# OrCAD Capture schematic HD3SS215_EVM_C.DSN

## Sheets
1 Page 1 Cover Page
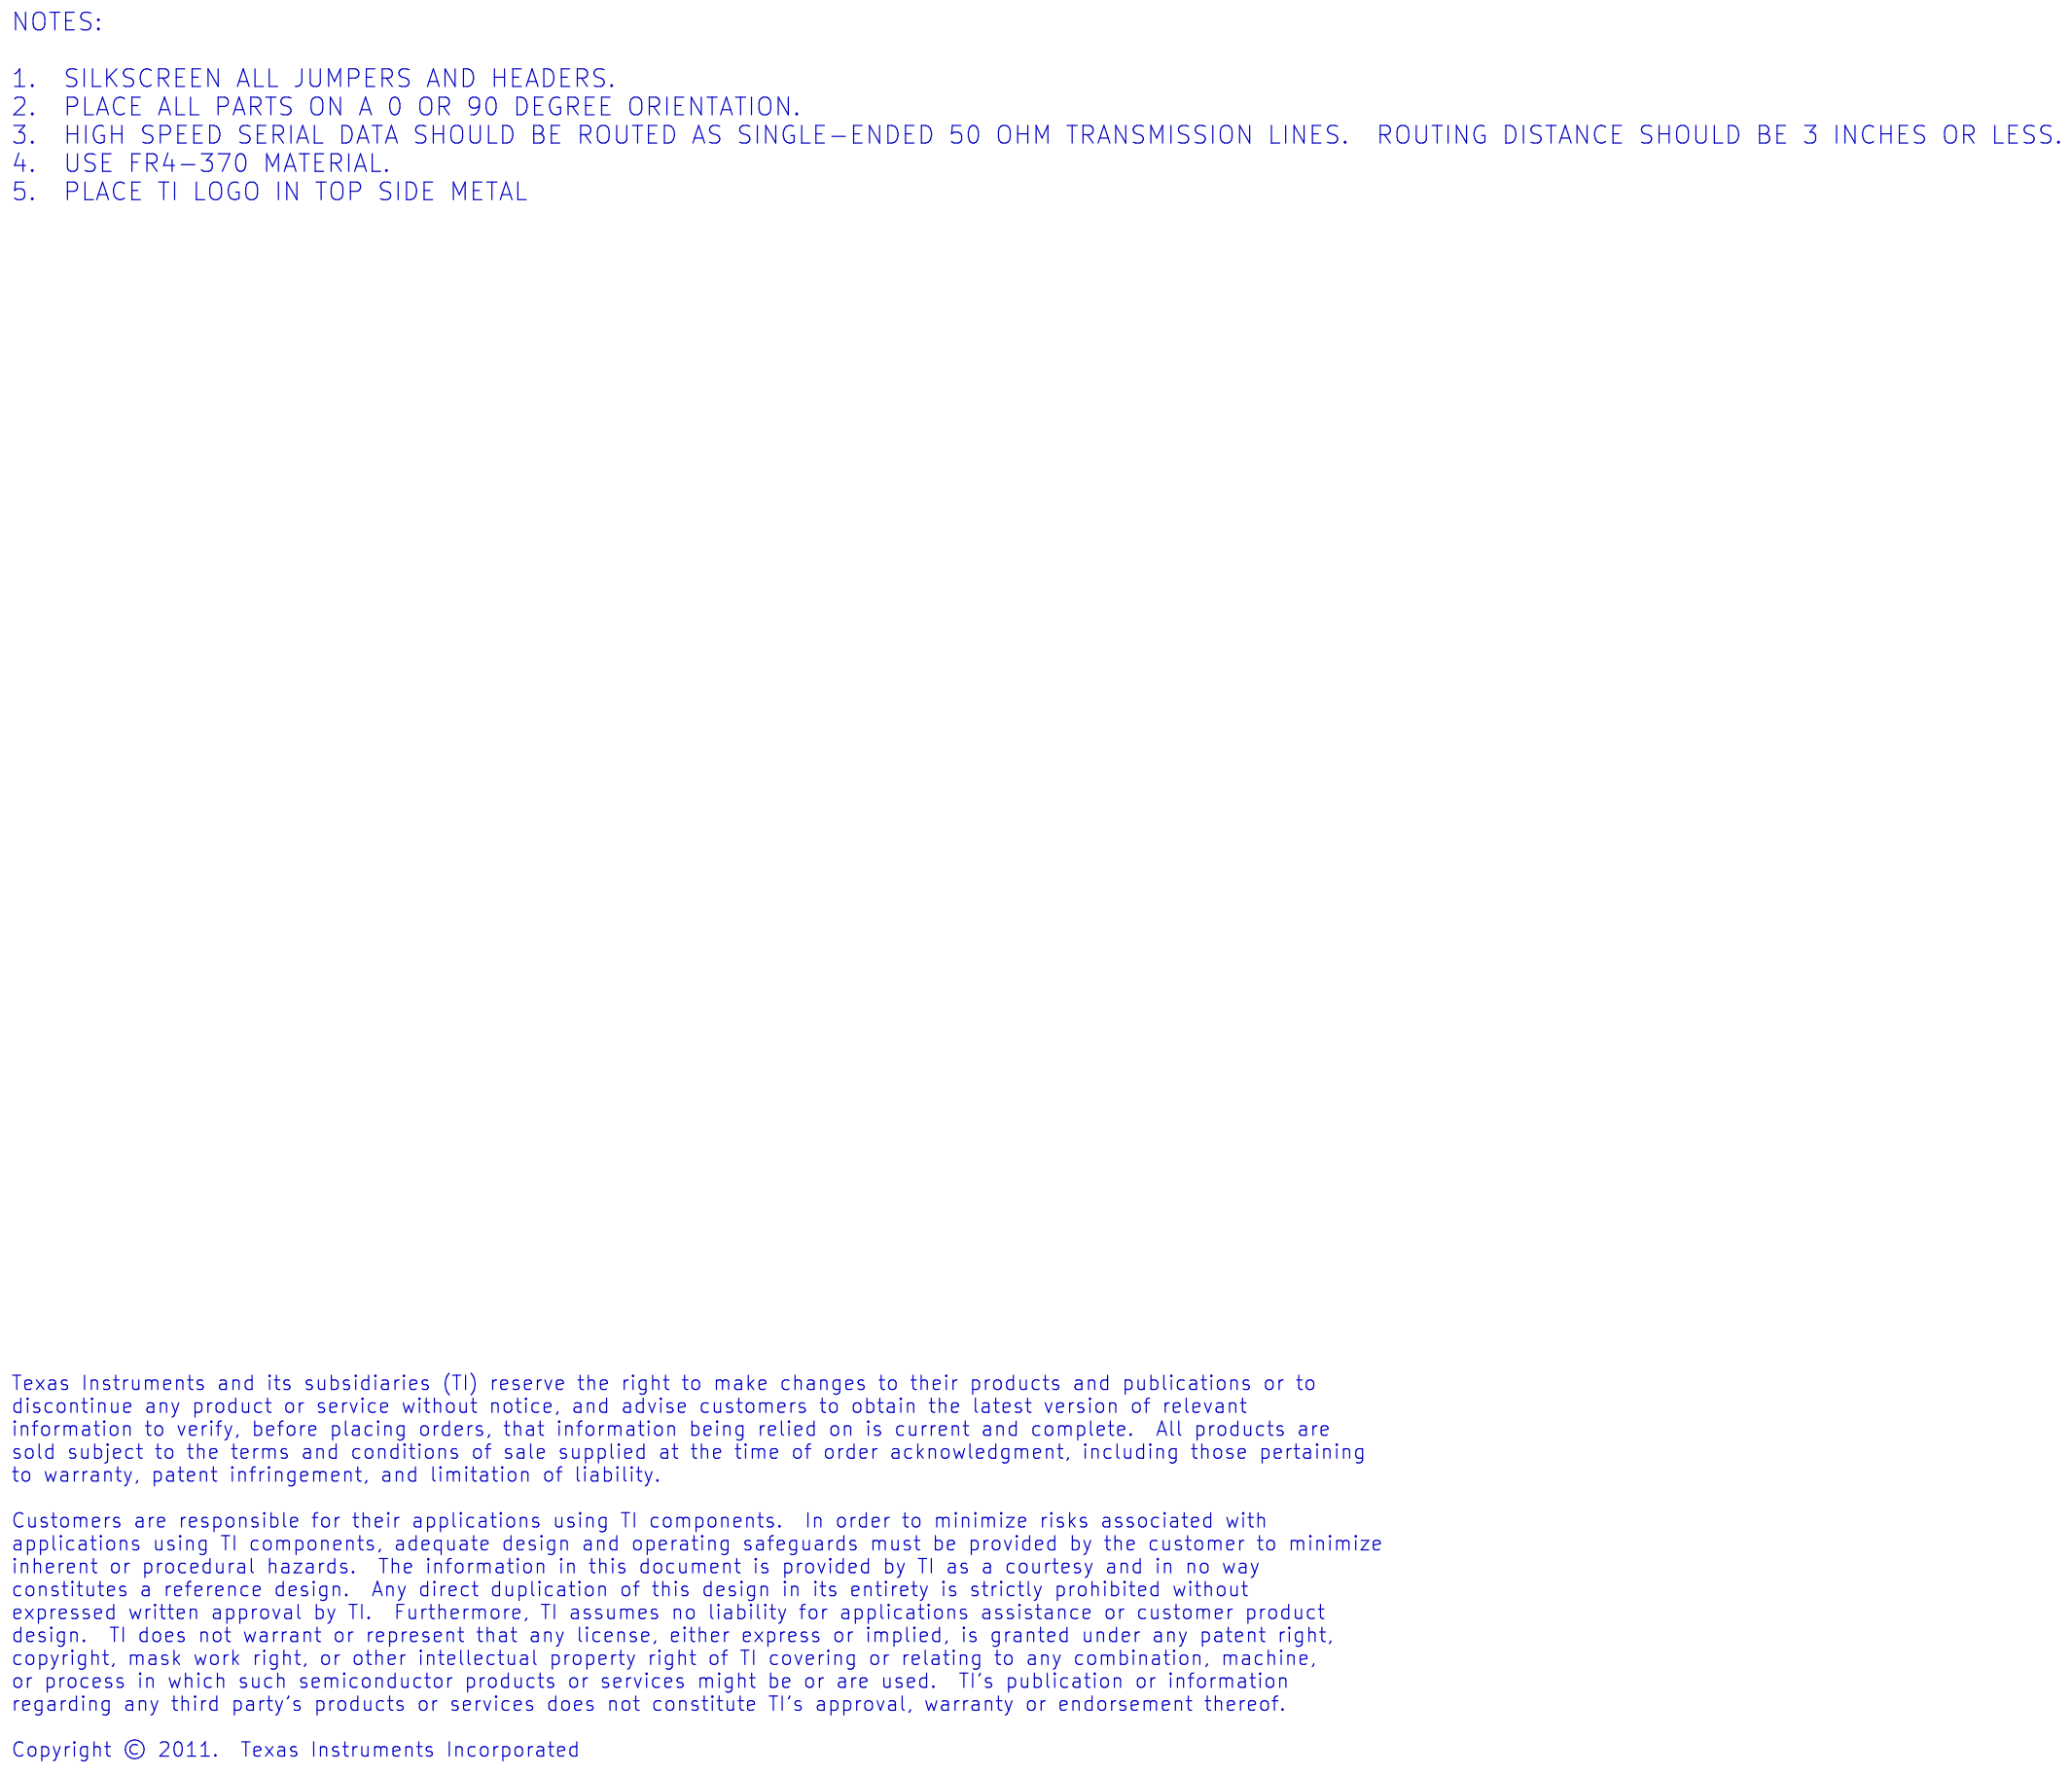
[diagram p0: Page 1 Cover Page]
2 Page 2 Source Port C: size B; note: 6516396
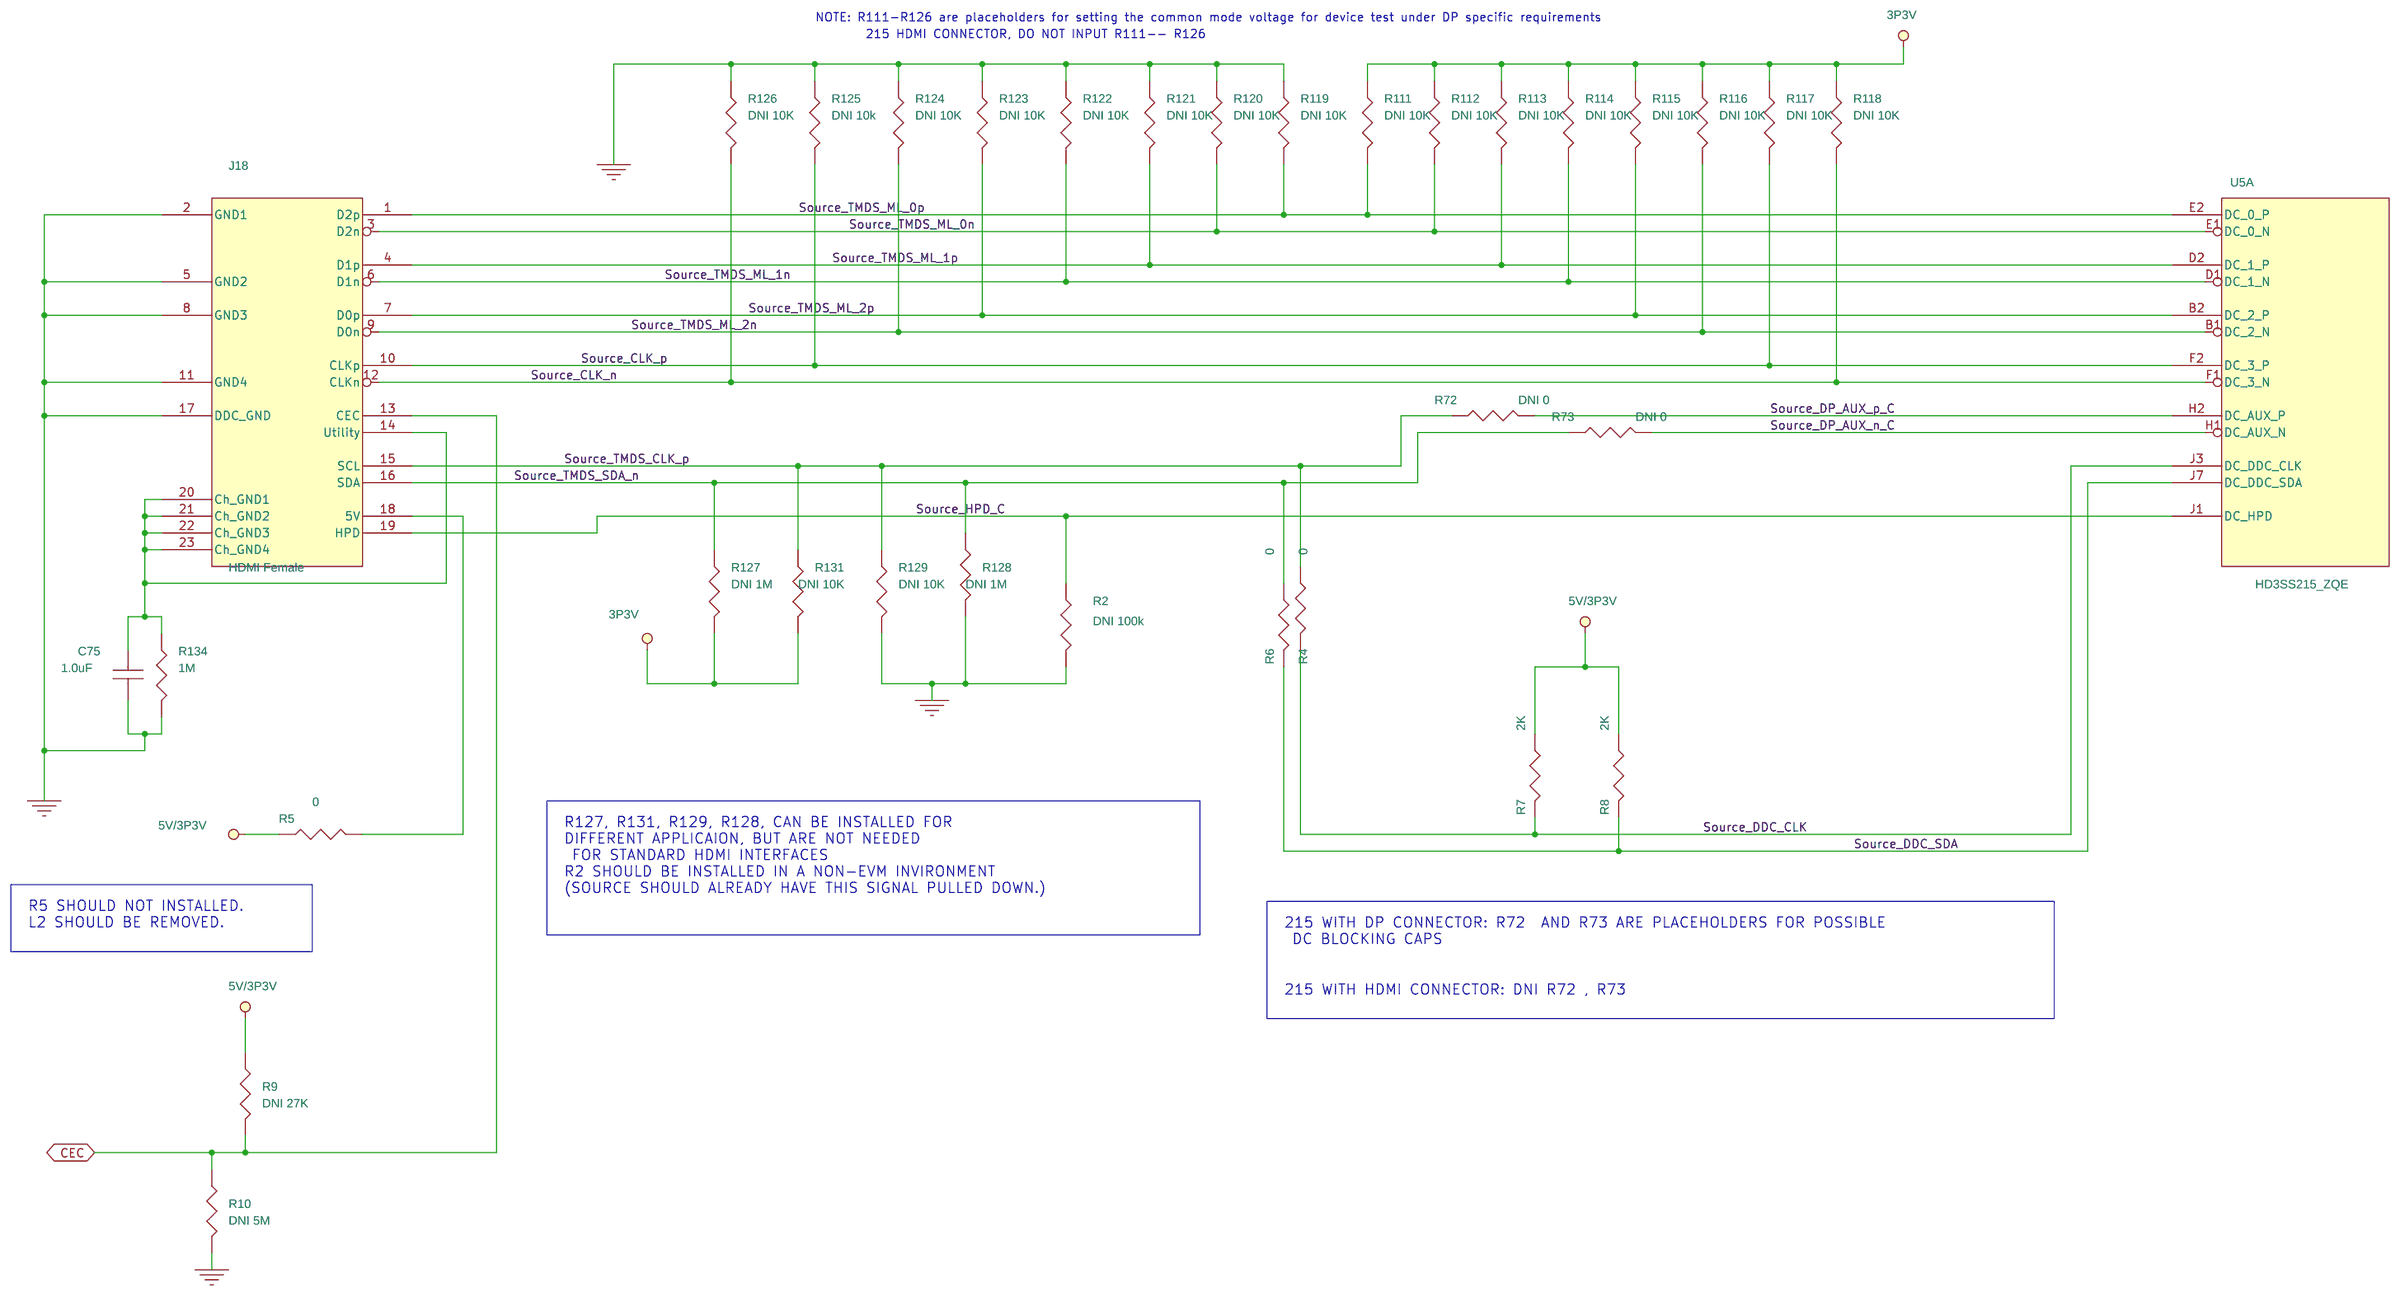
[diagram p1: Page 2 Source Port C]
3 Page 3 Sink Port A and B: size Custom; note: 6516396
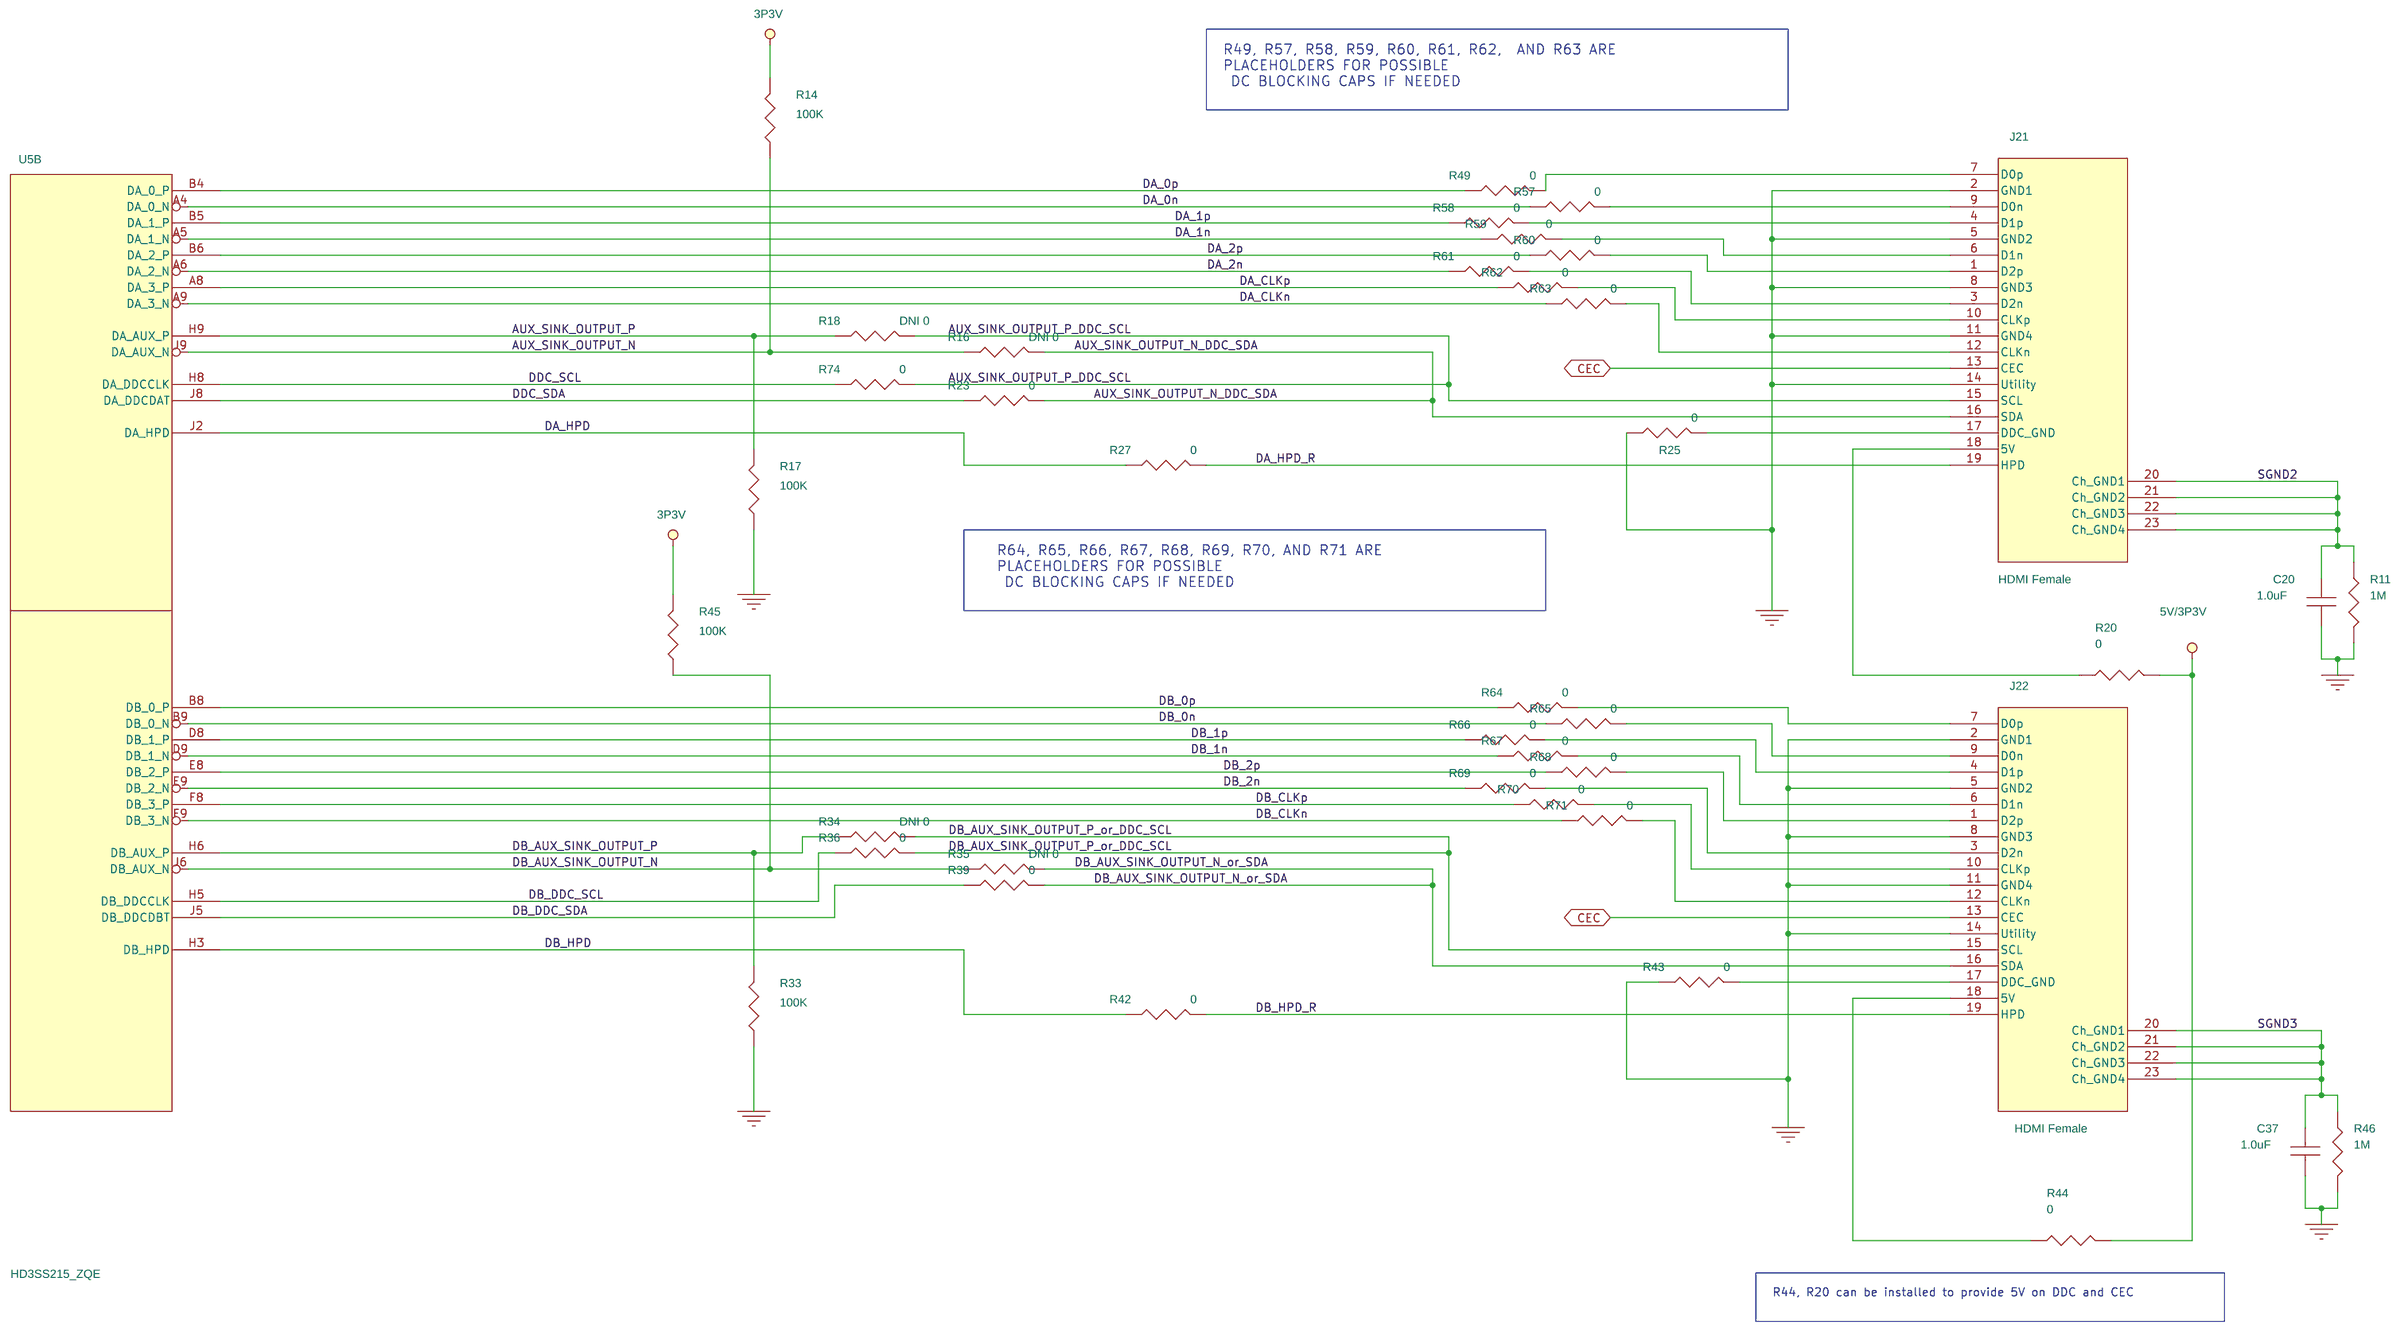
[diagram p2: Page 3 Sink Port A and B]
4 Page 4 CONTROL: size B; note: 6516396
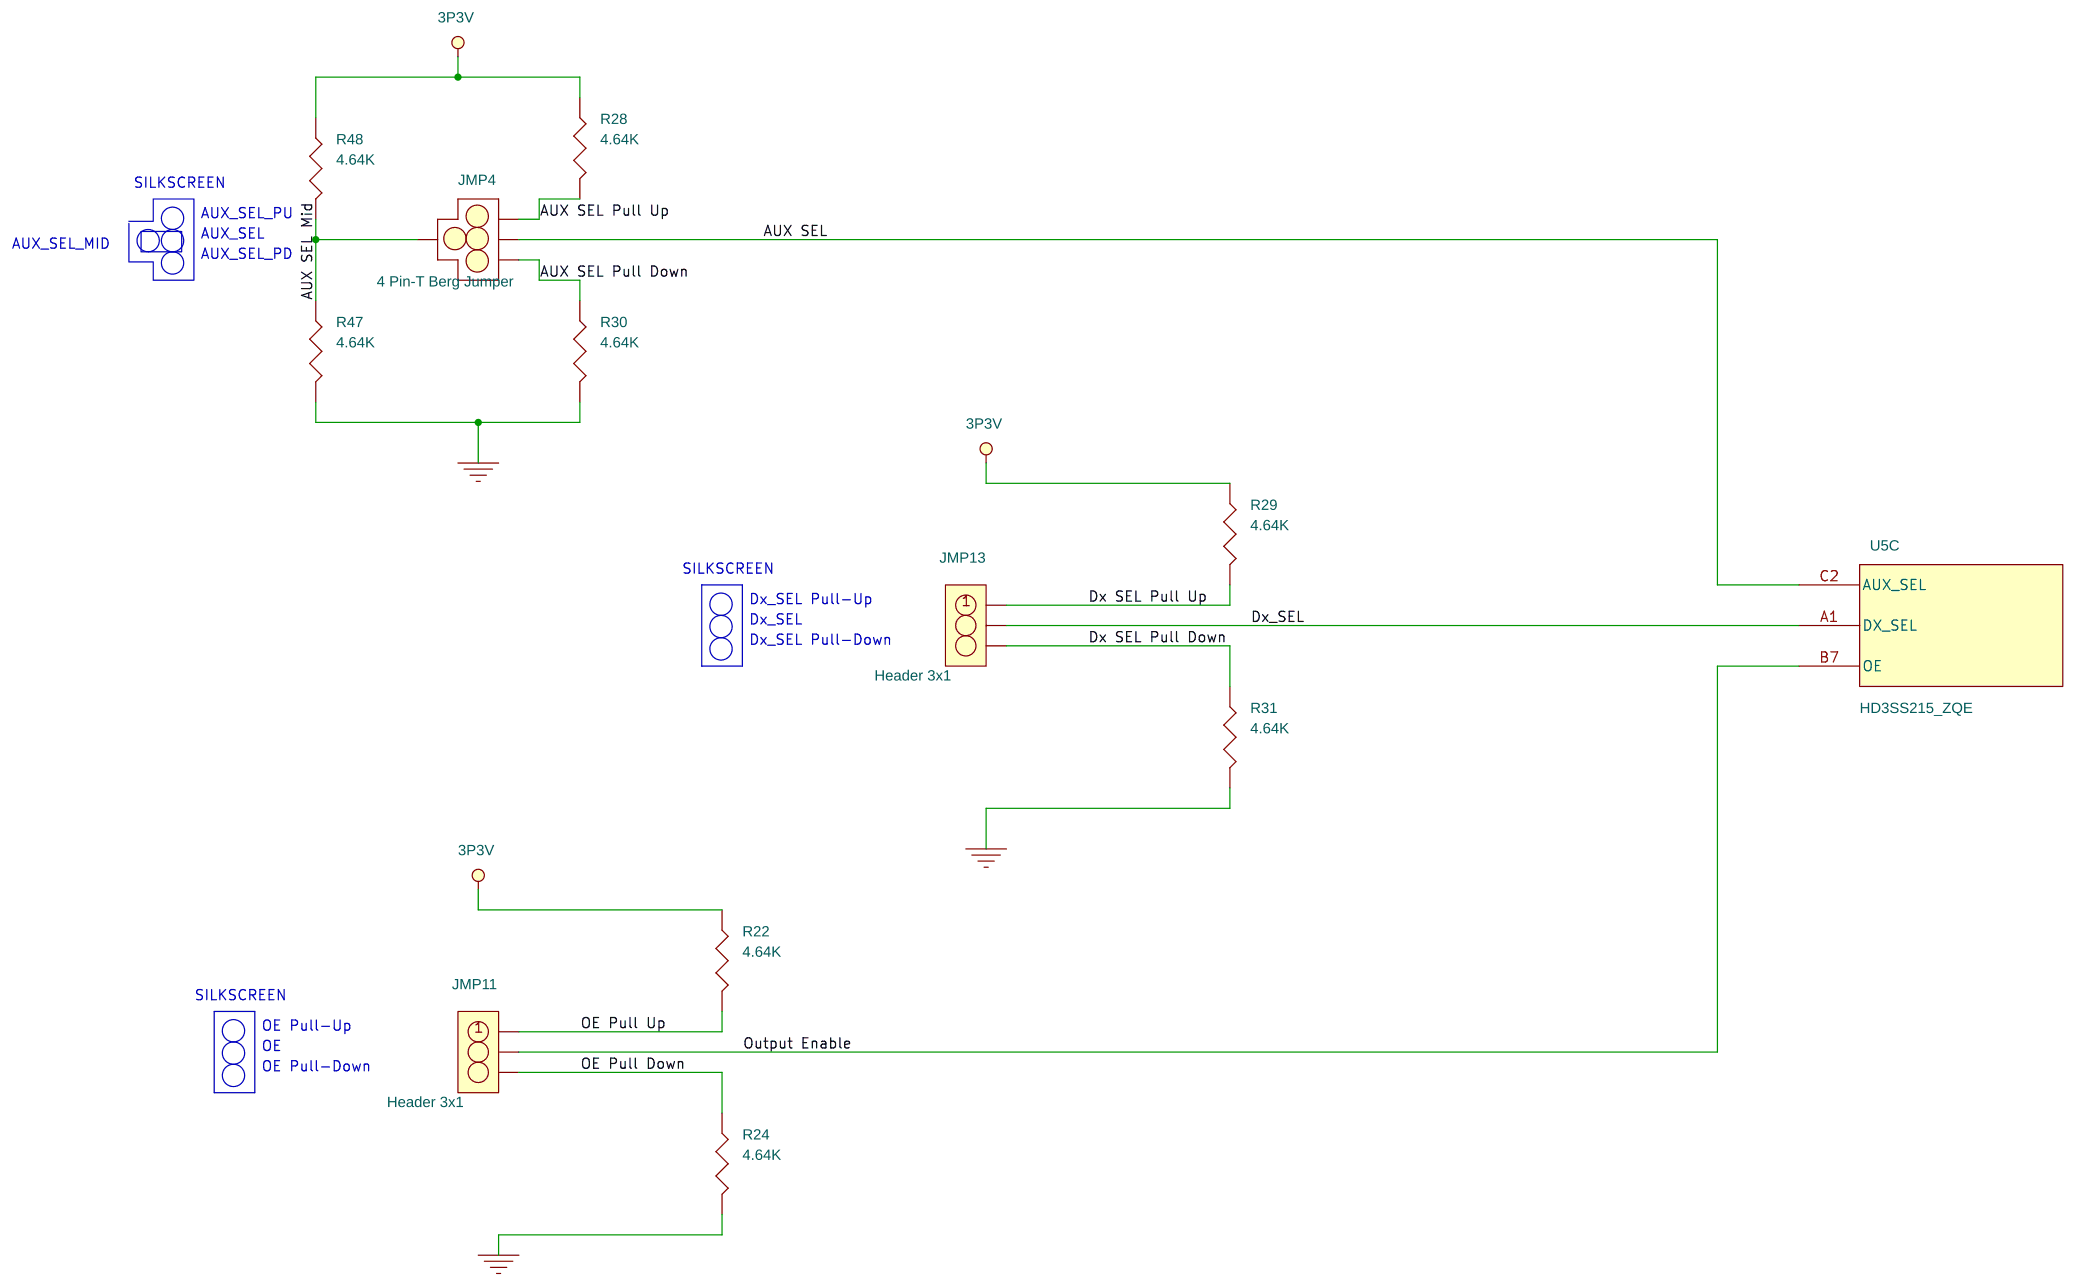
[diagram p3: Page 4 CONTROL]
5 Page 5 Power: size B; note: 6516396
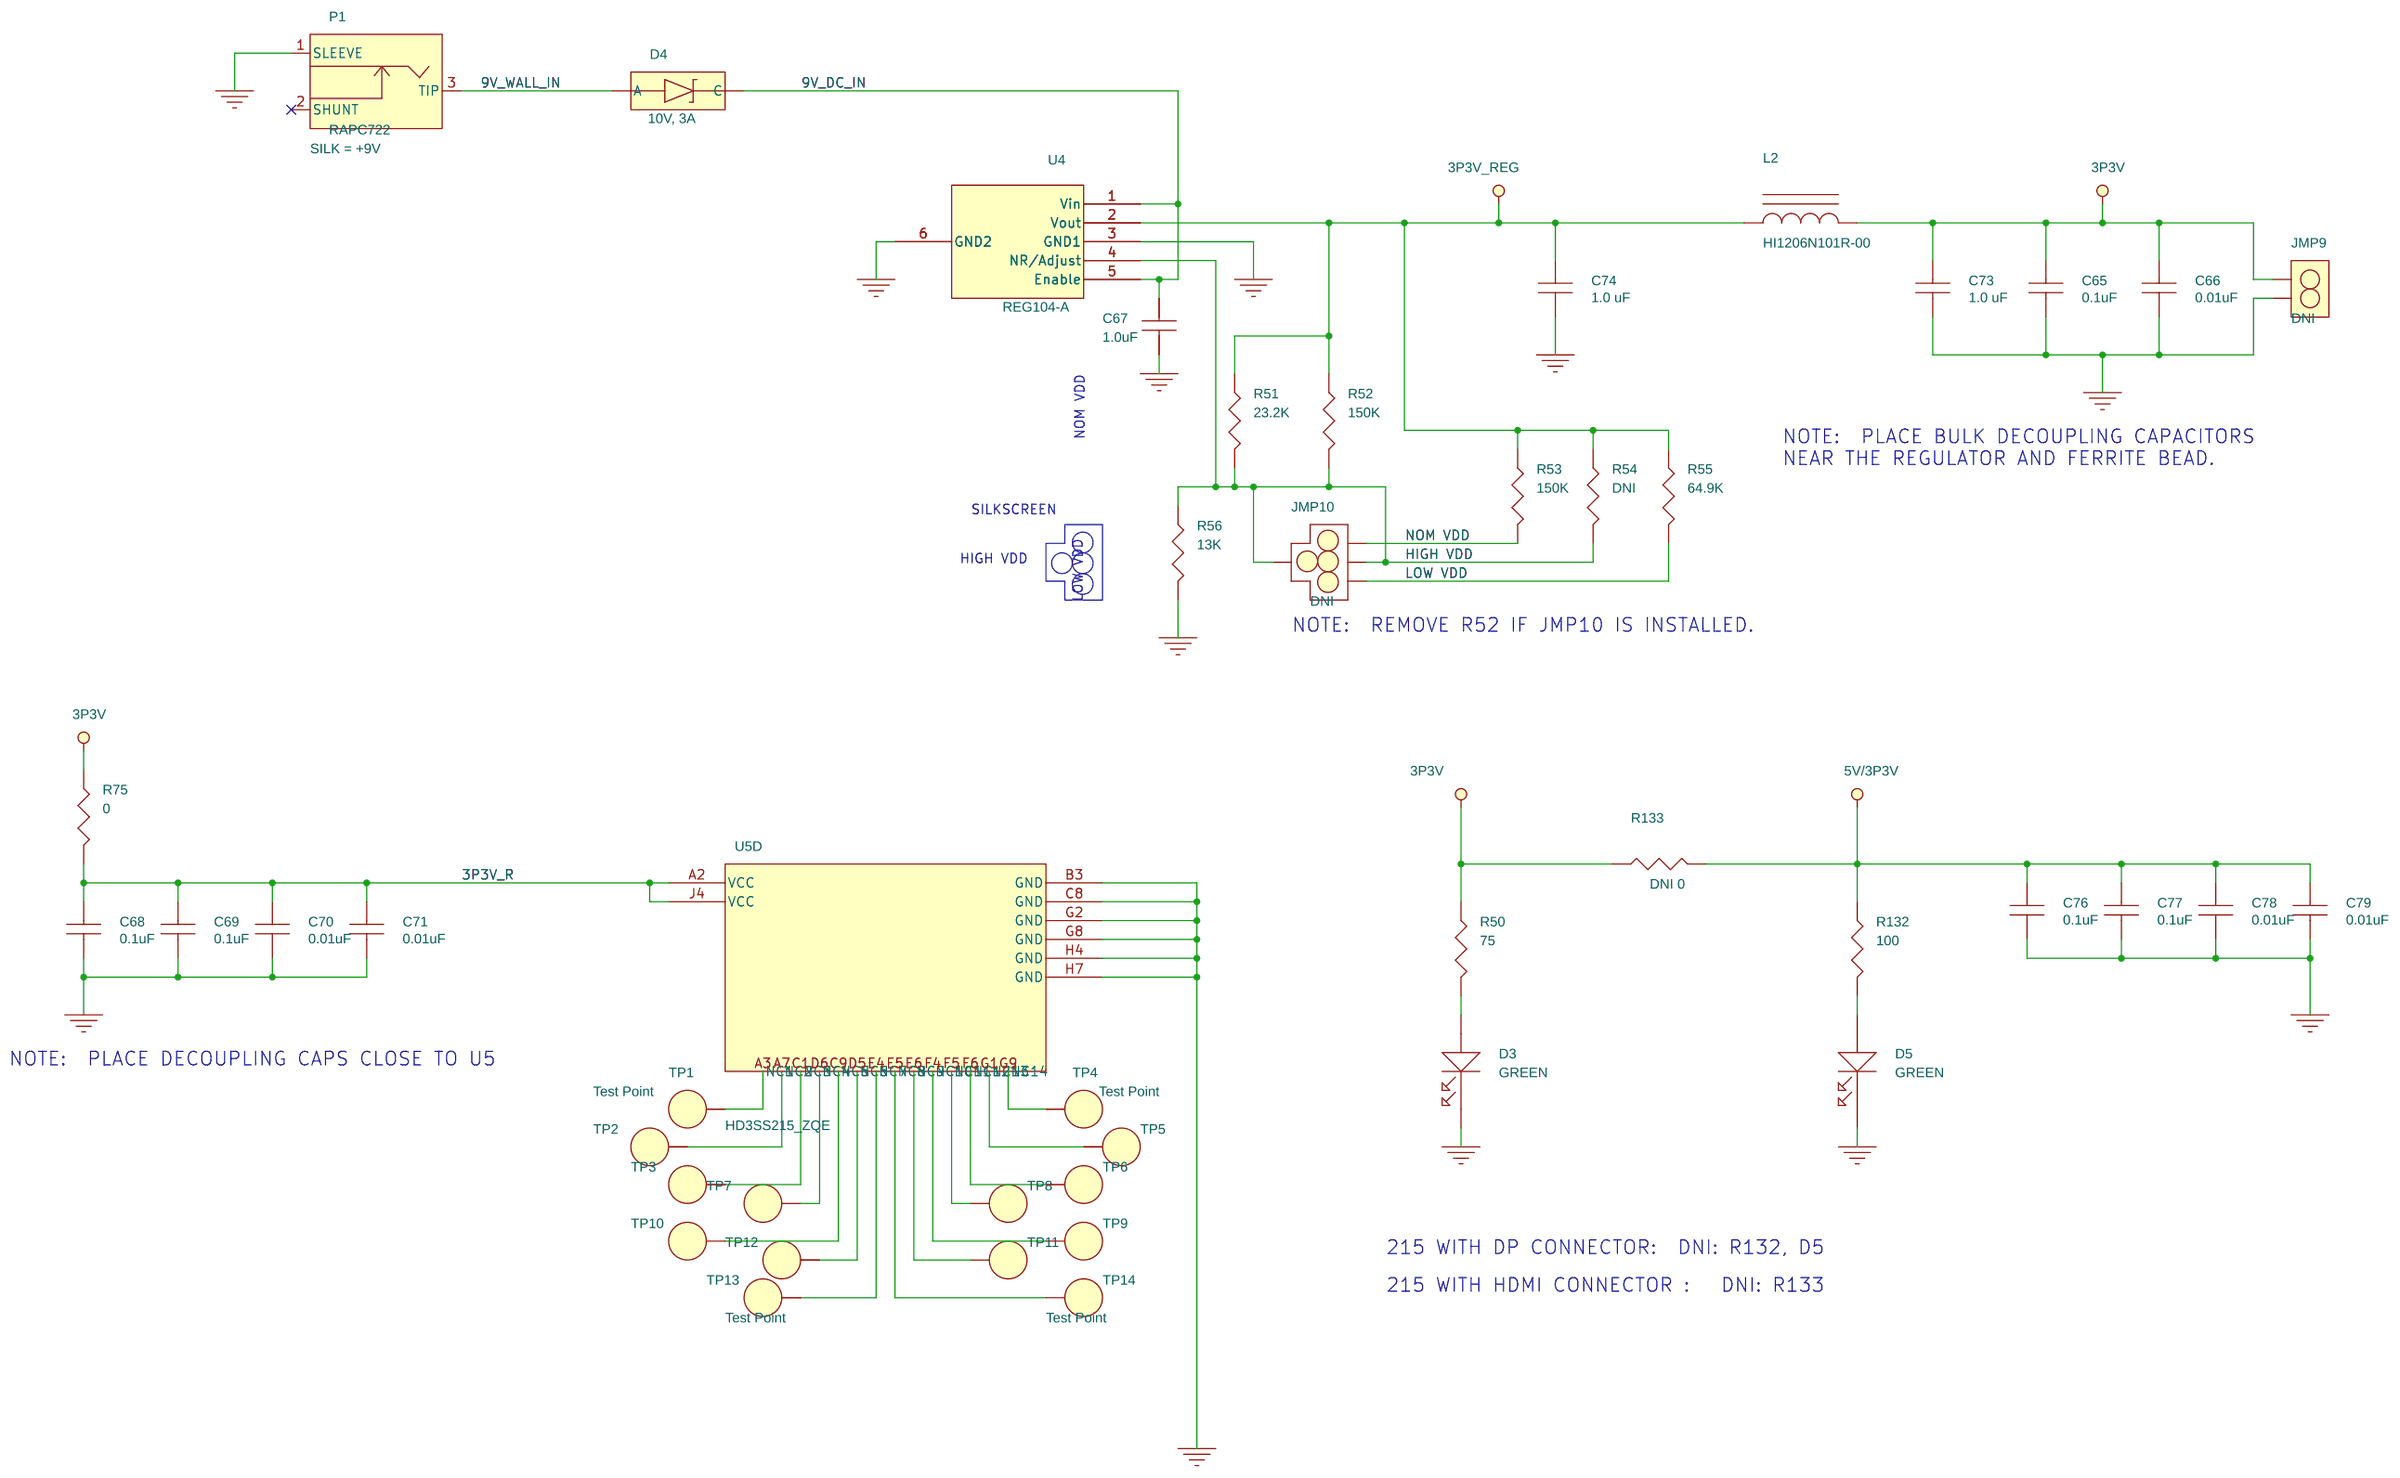
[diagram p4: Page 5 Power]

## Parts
sheet Page 2 Source Port C
C75  1.0uF  [0603]
J18  HDMI Female  [molex_hdmi]
R2  DNI 100k  [0402]
R4  0  [0201]
R5  0  [0402]
R6  0  [0201]
R7  2K  [0402]
R8  2K  [0402]
R9  DNI 27K  [0402]
R10  DNI 5M  [0402]
R72  DNI 0  [0201]
R73  DNI 0  [0201]
R111  DNI 10K  [0201]
R112  DNI 10K  [0201]
R113  DNI 10K  [0201]
R114  DNI 10K  [0201]
R115  DNI 10K  [0201]
R116  DNI 10K  [0201]
R117  DNI 10K  [0201]
R118  DNI 10K  [0201]
R119  DNI 10K  [0201]
R120  DNI 10K  [0201]
R121  DNI 10K  [0201]
R122  DNI 10K  [0201]
R123  DNI 10K  [0201]
R124  DNI 10K  [0201]
R125  DNI 10k  [0201]
R126  DNI 10K  [0201]
R127  DNI 1M  [0201]
R128  DNI 1M  [0201]
R129  DNI 10K  [0201]
R131  DNI 10K  [0201]
R134  1M  [0603]
U5  HD3SS215_ZQE  [IRONWOOD_81PIN_7048]  (sections A,B,C,D)
sheet Page 3 Sink Port A and B
C20  1.0uF  [0603]
C37  1.0uF  [0603]
J21  HDMI Female  [molex_hdmi]
J22  HDMI Female  [molex_hdmi]
R11  1M  [0603]
R14  100K  [0402]
R16  DNI 0  [0201]
R17  100K  [0402]
R18  DNI 0  [0201]
R20  0  [0402]
R23  0  [0201]
R25  0  [0201]
R27  0  [0201]
R33  100K  [0402]
R34  DNI 0  [0201]
R35  DNI 0  [0201]
R36  0  [0201]
R39  0  [0201]
R42  0  [0201]
R43  0  [0201]
R44  0  [0402]
R45  100K  [0402]
R46  1M  [0603]
R49  0  [0201]
R57  0  [0201]
R58  0  [0201]
R59  0  [0201]
R60  0  [0201]
R61  0  [0201]
R62  0  [0201]
R63  0  [0201]
R64  0  [0201]
R65  0  [0201]
R66  0  [0201]
R67  0  [0201]
R68  0  [0201]
R69  0  [0201]
R70  0  [0201]
R71  0  [0201]
R74  0  [0201]
sheet Page 4 CONTROL
JMP4  4 Pin-T Berg Jumper  [berg2x3tee]
JMP11  Header 3x1  [berg1x3]
JMP13  Header 3x1  [berg1x3]
R22  4.64K  [0603]
R24  4.64K  [0603]
R28  4.64K  [0603]
R29  4.64K  [0603]
R30  4.64K  [0603]
R31  4.64K  [0603]
R47  4.64K  [0603]
R48  4.64K  [0603]
sheet Page 5 Power
C65  0.1uF  [0402]
C66  0.01uF  [0402]
C67  1.0uF  [0402]
C68  0.1uF  [0402]
C69  0.1uF  [0402]
C70  0.01uF  [0402]
C71  0.01uF  [0402]
C73  1.0 uF  [0402]
C74  1.0 uF  [0402]
C76  0.1uF  [0402]
C77  0.1uF  [0402]
C78  0.01uF  [0402]
C79  0.01uF  [0402]
D3  GREEN  [led_hsmb_c170dra]
D4  10V, 3A  [SOD323]
D5  GREEN  [led_hsmb_c170dra]
JMP9  DNI  [berg2]
JMP10  DNI  [berg2x3tee]
L2  HI1206N101R-00  [1210]
P1  RAPC722  [con_rapc722_jack_thvt_3]
R50  75  [0402]
R51  23.2K  [0603]
R52  150K  [0603]
R53  150K  [0603]
R54  DNI  [0603]
R55  64.9K  [0603]
R56  13K  [0603]
R75  0  [0603]
R132  100  [0402]
R133  DNI 0  [0402]
TP1  Test Point  [testpointdra]
TP2  Test Point  [testpointdra]
TP3  Test Point  [testpointdra]
TP4  Test Point  [testpointdra]
TP5  Test Point  [testpointdra]
TP6  Test Point  [testpointdra]
TP7  Test Point  [testpointdra]
TP8  Test Point  [testpointdra]
TP9  Test Point  [testpointdra]
TP10  Test Point  [testpointdra]
TP11  Test Point  [testpointdra]
TP12  Test Point  [testpointdra]
TP13  Test Point  [testpointdra]
TP14  Test Point  [testpointdra]
U4  REG104-A  [DCQ_R-PDSO-G6]

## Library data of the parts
C20 C37 C75 = cc0603: Digikey_PN: 445-1604-2-ND
J18 = HDMI_A_plug_connector
R2 R5 R7-R10 R20 R23 R36 R39 R44 R54 R74 = r0402
R4 R6 R16 R18 R25 R27 R34 R35 R42 R43 R49 R57-R71 = r0402: Digikey_PN: P0.0AGTR-ND
R72 R73 = r0402: Digikey_PN: P0.0AGTR-ND; Manufacture: DK; Manufacture PN: 0 ohms
R111-R129 R131 = r0201
R11 R46 R134 = r0603: Digikey_PN: P1.00MHTR-ND
U5 = HD3SS213_ZQE_1
J21 J22 = HDMI_A_plug_connector1
R14 R17 R33 R45 = r0402: Digikey_PN: 311-100KLRTR-ND
JMP4 = 4_Pin-T_Berg_Jumper: Digikey_PN: HTSW-150-07-G-S-ND; Manufacturer: Samtec; Part_Number: HTSW-150-07-G-S
JMP11 JMP13 = Header_3x1: Digikey_PN: HTSW-150-07-G-S-ND; Manufacturer: Samtec; Part_Number: HTSW-150-07-G-S
R22 R24 R28-R31 R47 R48 = r0603: Digikey_PN: P4.64KHTR-ND
C65 C68 C69 C76 C77 = cc0402: Digikey_PN: 445-4952-2-ND
C66 C70 C71 C78 C79 = cc0402: Digikey_PN: 490-4516-2-ND
C67 = cc0402: Digikey_PN: 445-1415-2-ND
C73 C74 = cc0402: Digikey_PN: 445-1415-2-ND; PART_NUMBER: C1005X5R0J105M050BB
D3 D5 = LED_0603: Digikey_PN: 67-1553-2-ND
D4 = BAT60A: Digikey_PN: BAT60AE6327INCT-ND
JMP9 = 2_Pin_Berg_Jumper
JMP10 = 4_Pin-T_Berg_Jumper
L2 = Ferrite_Bead_1210_HI1206N10R-00: Digikey_PN: 240-2408-2-ND
P1 = RAPC722: Digikey_PN: CP-002AH-ND; SILK: +9V
R50 R132 = r0402: Digikey_PN: RHM75.0LTR-ND
R51 = r0402: Digikey_PN: P23.2KHTR-ND
R52 R53 = r0402: Digikey_PN: P150KHTR-ND
R55 = r0402: Digikey_PN: P64.9KHTR-ND
R56 = r0402: Digikey_PN: P13.0KHTR-ND
R75 = r0402: Digikey_PN: P10AXTR-ND
R133 = R
TP1-TP14 = Test_Point
U4 = REG104: Digikey_PN: REG104GA-A-ND

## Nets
9V_DC_IN: C67.1 D4.1(C) U4.1(Vin) U4.5(Enable)
9V_WALL_IN: D4.2(A) P1.3(TIP)
GND: C20.2 C37.2 C65.2 C66.2 C67.2 C68.2 C69.2 C70.2 C71.2 C73.2 C74.2 C75.2 C76.2 C77.2 C78.2 C79.2 D3.1 D5.1 J18.2(GND1) J18.5(GND2) J18.8(GND3) J18.11(GND4) J18.17(DDC_GND) J21.2(GND1) J21.5(GND2) J21.8(GND3) J21.11(GND4) J21.14(Utility) J22.2(GND1) J22.5(GND2) J22.8(GND3) J22.11(GND4) J22.14(Utility) JMP9.2 P1.1(SLEEVE) R2.1 R10.2 R11.2 R17.1 R24.2 R25.1 R30.2 R31.2 R33.1 R43.1 R46.2 R47.2 R56.2 R119.1 R120.1 R121.1 R122.1 R123.1 R124.1 R125.1 R126.1 R128.2 R129.2 R134.2 U4.3(GND1) U4.6(GND2) U5.B3(GND) U5.C8(GND) U5.G2(GND) U5.G8(GND) U5.H4(GND) U5.H7(GND)
SGND2: C20.1 J21.20(Ch_GND1) J21.21(Ch_GND2) J21.22(Ch_GND3) J21.23(Ch_GND4) R11.1
SGND3: C37.1 J22.20(Ch_GND1) J22.21(Ch_GND2) J22.22(Ch_GND3) J22.23(Ch_GND4) R46.1
3P3V: C65.1 C66.1 C73.1 JMP9.1 L2.2 R14.2 R22.1 R28.1 R29.1 R45.2 R48.1 R50.1 R75.1 R111.1 R112.1 R113.1 R114.1 R115.1 R116.1 R117.1 R118.1 R127.2 R131.2 R133.1
3P3V_R: C68.1 C69.1 C70.1 C71.1 R75.2 U5.A2(VCC) U5.J4(VCC)
3P3V_REG: C74.1 L2.1 R51.1 R52.1 R53.1 R54.1 R55.1 U4.2(Vout)
5V/3P3V: C76.1 C77.1 C78.1 C79.1 R5.1 R7.1 R8.1 R9.1 R20.2 R44.2 R132.1 R133.2
AUX SEL: JMP4.2 U5.C2(AUX_SEL)
AUX SEL Mid: JMP4.4 R47.1 R48.2
AUX SEL Pull Down: JMP4.3 R30.1
AUX SEL Pull Up: JMP4.1 R28.2
AUX_SINK_OUTPUT_N: R14.1 R16.1 U5.J9(DA_AUX_N)
AUX_SINK_OUTPUT_N_DDC_SDA: J21.16(SDA) R16.2 R23.2
AUX_SINK_OUTPUT_P: R17.2 R18.1 U5.H9(DA_AUX_P)
AUX_SINK_OUTPUT_P_DDC_SCL: J21.15(SCL) R18.2 R74.2
CEC: J18.13(CEC) J21.13(CEC) J22.13(CEC) R9.2 R10.1
DA_0n: R57.1 U5.A4(DA_0_N)
DA_0p: R49.1 U5.B4(DA_0_P)
DA_1n: R59.1 U5.A5(DA_1_N)
DA_1p: R58.1 U5.B5(DA_1_P)
DA_2n: R61.1 U5.A6(DA_2_N)
DA_2p: R60.1 U5.B6(DA_2_P)
DA_CLKn: R63.1 U5.A9(DA_3_N)
DA_CLKp: R62.1 U5.A8(DA_3_P)
DA_HPD: R27.1 U5.J2(DA_HPD)
DA_HPD_R: J21.19(HPD) R27.2
DB_0n: R65.1 U5.B9(DB_0_N)
DB_0p: R64.1 U5.B8(DB_0_P)
DB_1n: R67.1 U5.D9(DB_1_N)
DB_1p: R66.1 U5.D8(DB_1_P)
DB_2n: R69.1 U5.E9(DB_2_N)
DB_2p: R68.1 U5.E8(DB_2_P)
DB_AUX_SINK_OUTPUT_N: R35.1 R45.1 U5.J6(DB_AUX_N)
DB_AUX_SINK_OUTPUT_N_or_SDA: J22.16(SDA) R35.2 R39.2
DB_AUX_SINK_OUTPUT_P: R33.2 R34.1 U5.H6(DB_AUX_P)
DB_AUX_SINK_OUTPUT_P_or_DDC_SCL: J22.15(SCL) R34.2 R36.2
DB_CLKn: R71.1 U5.F9(DB_3_N)
DB_CLKp: R70.1 U5.F8(DB_3_P)
DB_DDC_SCL: R36.1 U5.H5(DB_DDCCLK)
DB_DDC_SDA: R39.1 U5.J5(DB_DDCDBT)
DB_HPD: R42.1 U5.H3(DB_HPD)
DB_HPD_R: J22.19(HPD) R42.2
DDC_SCL: R74.1 U5.H8(DA_DDCCLK)
DDC_SDA: R23.1 U5.J8(DA_DDCDAT)
Dx SEL Pull Down: JMP13.3 R31.1
Dx SEL Pull Up: JMP13.1 R29.2
Dx_SEL: JMP13.2 U5.A1(DX_SEL)
HIGH VDD: JMP10.2 JMP10.4 R51.2 R52.2 R54.2 R56.1 U4.4(NR/Adjust)
LOW VDD: JMP10.3 R55.2
NOM VDD: JMP10.1 R53.2
OE Pull Down: JMP11.3 R24.1
OE Pull Up: JMP11.1 R22.2
Output Enable: JMP11.2 U5.B7(OE)
Source_CLK_n: J18.12(CLKn) R118.2 R126.2 U5.F1(DC_3_N)
Source_CLK_p: J18.10(CLKp) R117.2 R125.2 U5.F2(DC_3_P)
Source_DDC_CLK: R4.2 R7.2 U5.J3(DC_DDC_CLK)
Source_DDC_SDA: R6.2 R8.2 U5.J7(DC_DDC_SDA)
Source_DP_AUX_n_C: R73.2 U5.H1(DC_AUX_N)
Source_DP_AUX_p_C: R72.2 U5.H2(DC_AUX_P)
Source_HPD_C: J18.19(HPD) R2.2 U5.J1(DC_HPD)
Source_TMDS_CLK_p: J18.15(SCL) R4.1 R72.1 R129.1 R131.1
Source_TMDS_ML_0n: J18.3(D2n) R112.2 R120.2 U5.E1(DC_0_N)
Source_TMDS_ML_0p: J18.1(D2p) R111.2 R119.2 U5.E2(DC_0_P)
Source_TMDS_ML_1n: J18.6(D1n) R114.2 R122.2 U5.D1(DC_1_N)
Source_TMDS_ML_1p: J18.4(D1p) R113.2 R121.2 U5.D2(DC_1_P)
Source_TMDS_ML_2n: J18.9(D0n) R116.2 R124.2 U5.B1(DC_2_N)
Source_TMDS_ML_2p: J18.7(D0p) R115.2 R123.2 U5.B2(DC_2_P)
Source_TMDS_SDA_n: J18.16(SDA) R6.1 R73.1 R127.1 R128.1
N16816313: D3.2 R50.2
N16845167: J18.18(5V) R5.2
N17461751: J21.7(D0p) R49.2
N17461760: J21.9(D0n) R57.2
N17461769: J21.4(D1p) R58.2
N17461772: J21.6(D1n) R59.2
N17461775: J21.1(D2p) R60.2
N17461784: J21.3(D2n) R61.2
N17461793: J21.10(CLKp) R62.2
N17461802: J21.12(CLKn) R63.2
N17518625: J21.18(5V) R20.1
N17521117: J22.7(D0p) R64.2
N17521123: J22.9(D0n) R65.2
N17521129: J22.4(D1p) R66.2
N17521131: J22.6(D1n) R67.2
N17521133: J22.1(D2p) R68.2
N17521137: J22.3(D2n) R69.2
N17521143: J22.10(CLKp) R70.2
N17521149: J22.12(CLKn) R71.2
N17522573: J22.17(DDC_GND) R43.2
N17522869: J22.18(5V) R44.1
N17527182: TP1.1 U5.A3(NC1)
N17527888: TP2.1 U5.A7(NC2)
N17528001: TP3.1 U5.C1(NC3)
N17528028: TP4.1 U5.G9(NC14)
N17528033: TP5.1 U5.G1(NC13)
N17528049: TP6.1 U5.F6(NC12)
N17528125: TP8.1 U5.F5(NC11)
N17528132: TP7.1 U5.D6(NC4)
N17528155: TP10.1 U5.C9(NC5)
N17528163: TP9.1 U5.F4(NC10)
N17528201: TP12.1 U5.D5(NC6)
N17528206: TP11.1 U5.E6(NC9)
N17528242: TP13.1 U5.E4(NC7)
N17528247: TP14.1 U5.E5(NC8)
N17577047: D5.2 R132.2
N17584630: J21.17(DDC_GND) R25.2
N17593880: C75.1 J18.14(Utility) J18.20(Ch_GND1) J18.21(Ch_GND2) J18.22(Ch_GND3) J18.23(Ch_GND4) R134.1

Not connected (* = marked no-connect by the designer): P1 2(SHUNT)*

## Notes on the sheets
sheet 1
- NOTES:
  1.  SILKSCREEN ALL JUMPERS AND HEADERS.
  2.  PLACE ALL PARTS ON A 0 OR 90 DEGREE ORIENTATION.
  3.  HIGH SPEED SERIAL DATA SHOULD BE ROUTED AS SINGLE-ENDED 50 OHM TRANSMISSION LINES.  ROUTING DISTANCE SHOULD BE 3 INCHES OR LESS.
  4.  USE FR4-370 MATERIAL.
  5.  PLACE TI LOGO IN TOP SIDE METAL
- Texas Instruments and its subsidiaries (TI) reserve the right to make changes to their products and publications or to
  discontinue any product or service without notice, and advise customers to obtain the latest version of relevant
  information to verify, before placing orders, that information being relied on is current and complete.  All products are
  sold subject to the terms and conditions of sale supplied at the time of order acknowledgment, including those pertaining
  to warranty, patent infringement, and limitation of liability.
  Customers are responsible for their applications using TI components.  In order to minimize risks associated with
  applications using TI components, adequate design and operating safeguards must be provided by the customer to minimize
  inherent or procedural hazards.  The information in this document is provided by TI as a courtesy and in no way
  constitutes a reference design.  Any direct duplication of this design in its entirety is strictly prohibited without
  expressed written approval by TI.  Furthermore, TI assumes no liability for applications assistance or customer product
  design.  TI does not warrant or represent that any license, either express or implied, is granted under any patent right,
  copyright, mask work right, or other intellectual property right of TI covering or relating to any combination, machine,
  or process in which such semiconductor products or services might be or are used.  TI’s publication or information
  regarding any third party’s products or services does not constitute TI’s approval, warranty or endorsement thereof.
  Copyright © 2011.  Texas Instruments Incorporated
sheet 2
- NOTE: R111-R126 are placeholders for setting the common mode voltage for device test under DP specific requirements
- 215 HDMI CONNECTOR, DO NOT INPUT R111-- R126
- R127, R131, R129, R128, CAN BE INSTALLED FOR
  DIFFERENT APPLICAION, BUT ARE NOT NEEDED
   FOR STANDARD HDMI INTERFACES
  R2 SHOULD BE INSTALLED IN A NON-EVM INVIRONMENT
  (SOURCE SHOULD ALREADY HAVE THIS SIGNAL PULLED DOWN.)
- R5 SHOULD NOT INSTALLED.
  L2 SHOULD BE REMOVED.
- 215 WITH DP CONNECTOR: R72  AND R73 ARE PLACEHOLDERS FOR POSSIBLE
   DC BLOCKING CAPS
- 215 WITH HDMI CONNECTOR: DNI R72 , R73
sheet 3
- R49, R57, R58, R59, R60, R61, R62,  AND R63 ARE
  PLACEHOLDERS FOR POSSIBLE
   DC BLOCKING CAPS IF NEEDED
- R64, R65, R66, R67, R68, R69, R70, AND R71 ARE
  PLACEHOLDERS FOR POSSIBLE
   DC BLOCKING CAPS IF NEEDED
- R44, R20 can be installed to provide 5V on DDC and CEC
sheet 4
- SILKSCREEN
- AUX_SEL_PU
- AUX_SEL_MID
- AUX_SEL
- AUX_SEL_PD
- SILKSCREEN
- Dx_SEL Pull-Up
- Dx_SEL
- Dx_SEL Pull-Down
- SILKSCREEN
- OE Pull-Up
- OE
- OE Pull-Down
sheet 5
- NOTE:  PLACE BULK DECOUPLING CAPACITORS
  NEAR THE REGULATOR AND FERRITE BEAD.
- NOM VDD
- SILKSCREEN
- HIGH VDD
- LOW VDD
- NOTE:  REMOVE R52 IF JMP10 IS INSTALLED.
- NOTE:  PLACE DECOUPLING CAPS CLOSE TO U5
- 215 WITH DP CONNECTOR:  DNI: R132, D5
- 215 WITH HDMI CONNECTOR :   DNI: R133
